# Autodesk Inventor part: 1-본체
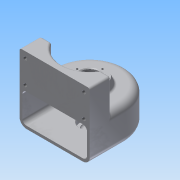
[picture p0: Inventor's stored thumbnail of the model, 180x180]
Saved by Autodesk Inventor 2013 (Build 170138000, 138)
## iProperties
Created: 2015-02
Part Number: 1-본체
Material: 알루미늄 6061
Document SubType Name: Modeling
Designer: Administrator
Density: 2.40731 g/cm^3
Mass: 511.244 g
Surface Area: 706.56 cm^2
Volume: 212.371 cm^3
Author: Administrator
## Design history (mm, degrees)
sketch "스케치1"
  geometry: L1 (-50, 0)-(-50, -50); L2 (-50, -50)-(50, -50); L3 (50, -50)-(50, 0); A1 r 50 centre (0, 0) between (-50, 0) and (50, 0); 1 further point
  constraints: 6 end point, 2 perpendicular, 2 point on circle, 1 centre point, 1 coincident, 1 tangent, 1 vertical
  dimensions: "d0" = 100 diameter of A1; "d2" = 50 distance from line of point (0, 0) L2; "d3" = 100 distance of L1.end L2.end
extrude "돌출1" new body sketch "스케치1" distance "d4" = 50; taper "d5" = 0 deg
fillet "모깎기1" dims "d6" = 10
feature "쉘1" dims "d7" = 4
node "작업 평면1"
sketch "스케치2"
  geometry: L1 (50, -50)-(40, -50) reference; L2 (40, -50)-(-40, -50) reference; L3 (-40, -50)-(-50, -50) reference; L4 (-50, -50)-(50, -50); L5 (50, -20)-(50, -50); L6 (-50, -20)-(-50, -50); L7 (50, 0)-(50, -50) reference; L8 (-50, -50)-(-50, 0) reference; L9 (50, -20)-(34.641, -20); L10 (-34.641, -20)-(-50, -20); A1 r 40 centre (0, 0) between (-34.641, -20) and (34.641, -20); 3 further points
  constraints: 10 end point, 4 collinear, 2 point on circle, 2 vertical alignment, 1 centre point, 1 coincident, 1 midpoint, 1 parallel, 1 point on line
  dimensions: "d9" = 80 diameter of A1; "d12" = 30 distance between parallel lines of L2 L9
extrude "돌출2" join sketch "스케치2" stored distance "d13" = 50; taper "d14" = 0 deg
sketch "스케치3"
  geometry: C1 r 25 at (0, 0); A1 r 40 centre (0, 0) between (-34.641, -20) and (34.641, -20) reference
  constraints: 1 centre point, 1 coincident
  dimensions: "d15" = 50 diameter of C1
extrude "돌출3" join sketch "스케치3" distance "d17" = 10; taper "d18" = -20 deg
hole "구멍1" diameter "d21" = 20; stored, may be unused: countersink angle "d25" = 90 deg, drill point angle "d27" = 0 deg; dims "d19" = 10, "d20" = 10, "d22" = 6, "d23" = 28, "d24" = 10, "d26" = 14
sketch "스케치4"
  geometry: C1 r 14 at (0, 0) reference; C2 r 21.36 at (0, 0) reference; A1 r 18 centre (0, 0) between (0, 18) and (0, -18); 2 further points
  constraints: 4 point on circle, 2 coincident, 2 horizontal alignment, 2 vertical alignment, 1 centre point
  dimensions: "d28" = 36 diameter of A1
hole "구멍2" sketch "스케치4" at (0, 18), (0, -18), (18, 0), (-18, 0) diameter "d30" = 2.459; stored, may be unused: countersink angle "d34" = 90 deg, drill point angle "d36" = 118 deg; dims "d31" = 6, "d32" = 28, "d33" = 10, "d35" = 9
sketch "스케치5"
  geometry: C1 r 20 at (0, 0); A1 r 40 centre (0, 0) between (40, 0) and (-40, 0) reference
  constraints: 1 centre point, 1 coincident
  dimensions: "d37" = 40 diameter of C1
extrude "돌출4" join sketch "스케치5" distance "d39" = 9; taper "d40" = 0 deg
hole "구멍3" diameter "d43" = 20; stored, may be unused: countersink angle "d47" = 90 deg, drill point angle "d49" = 0 deg; dims "d41" = 10, "d42" = 10, "d44" = 6, "d45" = 28, "d46" = 8, "d48" = 10
sketch "스케치6"
  geometry: L1 (90, 95)-(-10, 95) reference; L2 (-1.75, 53)-(81.75, 53); L3 (81.75, 53)-(81.75, 86); L4 (81.75, 86)-(-1.75, 86); L5 (-1.75, 86)-(-1.75, 53); 7 further points
  constraints: 8 end point, 4 coincident, 2 midpoint, 2 parallel, 1 horizontal, 1 perpendicular, 1 vertical alignment
  dimensions: "d50" = 9 distance between parallel lines of L4 L1; "d51" = 33 distance of L2.end L3.end; "d52" = 83.5 distance of L3.end L4.end
hole "구멍4" sketch "스케치6" at (-1.75, 86), (-1.75, 53), (81.75, 53), (81.75, 86) diameter "d53" = 5.134; stored, may be unused: countersink angle "d57" = 90 deg, drill point angle "d59" = 118 deg; dims "d54" = 10, "d55" = 28, "d56" = 8, "d58" = 13
chamfer "모따기1" distance "d60" = 1; stored, may be unused: second distance "d61" = 2, angle "d62" = 45 deg
fillet "모깎기2" dims "d63" = 0.3, "d64" = 3
node "작업 평면2"
sketch "스케치7"
  geometry: L1 (40, 0)-(-40, 0) reference; 2 further points
  constraints: 1 vertical alignment, 1 other
  dimensions: "d65" = 25 distance from line of point (0, 25) L1
feature "엠보싱1" sketch "스케치7" dims "d9" = 80, "d12" = 30, "d66" = 0.5, "d67" = 0
node "솔리드1"
other parameters: "d8" = -95
